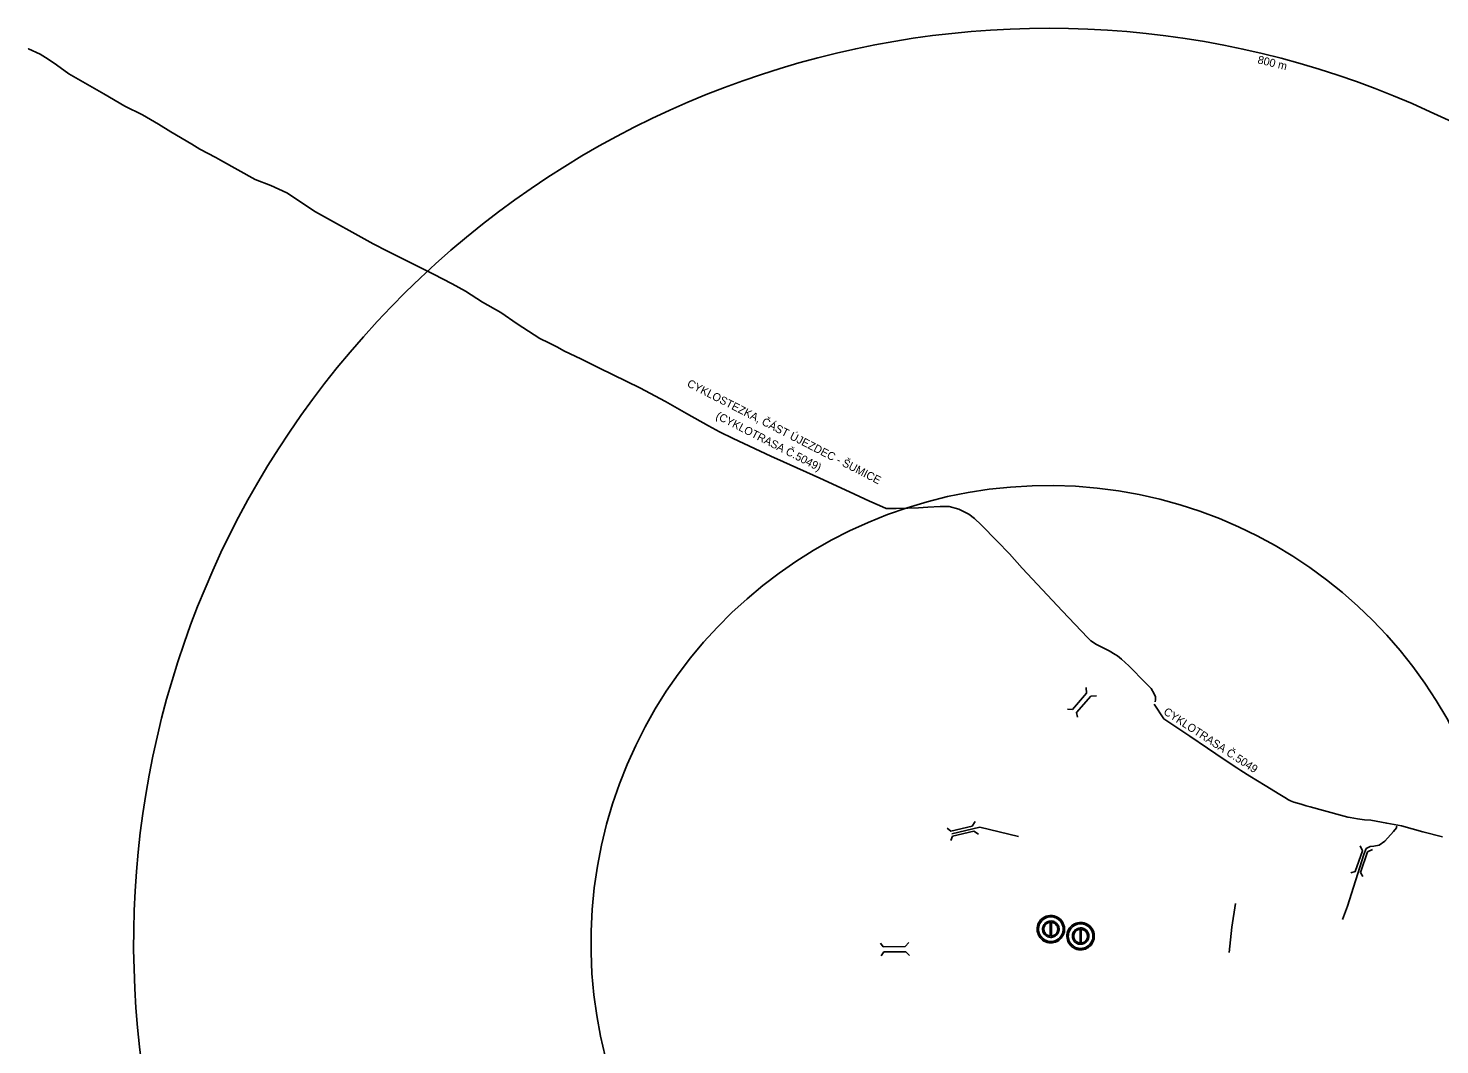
# Model space of a CAD drawing. Extents: x -520790 to -517278, y -1190021 to -1185077.
# Drawn here: x -520790 to -519555, y -1187341 to -1186452 of the extents above; entities that cross this region are included whole.
import ezdxf

# ---------------------------------------------------------------- set-up
doc = ezdxf.new("R2010")
doc.units = 0
for name, color, linetype in [('cyklostezka_s', 7, 'Continuous'), ('dostupnost_s', 7, 'Continuous'), ('most_s', 7, 'Continuous'), ('stezka_s', 7, 'Continuous'), ('zast_HD_s', 7, 'Continuous')]:
    doc.layers.add(name, color=color, linetype=linetype)

msp = doc.modelspace()

# ---------------------------------------------------------------- linework, layer by layer
at = {"layer": 'cyklostezka_s'}
for points in [[(-520790, -1186469.9), (-520789.7, -1186470), (-520779.6, -1186474.9), (-520772.5, -1186479.2), (-520765.3, -1186484.1), (-520754.5, -1186492), (-520740.3, -1186500.1), (-520724, -1186509.5), (-520705.4, -1186520.3), (-520690, -1186527.9), (-520676.1, -1186536), (-520665.4, -1186542.6), (-520647, -1186553.5), (-520639.8, -1186557.9), (-520625.8, -1186565.3), (-520621.8, -1186567.6), (-520606.7, -1186576.1), (-520591.6, -1186584.3), (-520577.7, -1186589.6), (-520563.9, -1186596.2), (-520538.7, -1186612.6), (-520488.3, -1186640.8), (-520475.8, -1186647.1), (-520435.6, -1186667.3), (-520419.3, -1186675.7), (-520407.6, -1186682.2), (-520392.6, -1186691.6), (-520376.7, -1186700.9), (-520362.3, -1186710.6), (-520342.5, -1186723.4), (-520334.6, -1186727.4), (-520327.6, -1186730.9), (-520321, -1186734.5), (-520306.8, -1186741.3), (-520290.5, -1186749.4), (-520255.1, -1186766.6), (-520232.5, -1186778.7), (-520214.3, -1186789.2), (-520195.1, -1186800), (-520185.3, -1186805.3), (-520173.5, -1186811), (-520140.6, -1186826.4), (-520129.4, -1186831.4), (-520097.7, -1186845.7), (-520071.8, -1186857.6), (-520054.2, -1186865.7), (-520045.6, -1186869.7), (-520039.5, -1186872.2), (-520030.9, -1186872.2), (-520020.8, -1186871.9), (-520011.4, -1186871.7), (-520003.3, -1186871.2), (-519992.5, -1186870.4), (-519984.4, -1186870.5), (-519976.2, -1186872.8), (-519967.3, -1186877.1), (-519962.3, -1186880.9), (-519956.6, -1186886.6), (-519942.5, -1186900.9), (-519931.8, -1186911.8), (-519920.8, -1186924.5), (-519885.4, -1186962), (-519863.4, -1186985.1), (-519860.5, -1186987.9), (-519855.6, -1186991.3), (-519844.7, -1186996.8), (-519839.2, -1186999.9), (-519837.2, -1187001.2), (-519833.9, -1187004.1), (-519827.4, -1187009.8), (-519812.6, -1187024.9), (-519808, -1187029.7), (-519805.1, -1187034.4), (-519804.2, -1187037), (-519804, -1187039.5), (-519804.3, -1187041.5)], [(-519805.2, -1187043.5), (-519796.9, -1187056.3), (-519789, -1187061.6), (-519774, -1187071.5), (-519758.5, -1187081.8), (-519758.5, -1187081.8), (-519744, -1187091.7), (-519733, -1187099.2), (-519729.5, -1187101.4), (-519721.6, -1187106.3), (-519708.2, -1187114.6), (-519695.4, -1187122.5), (-519691, -1187125.2), (-519687.8, -1187127.1), (-519686.1, -1187127.9), (-519683.1, -1187129.1), (-519676.8, -1187130.9), (-519672.4, -1187132.3), (-519668.7, -1187133.3), (-519642.4, -1187140.5), (-519635.9, -1187142.4), (-519633.9, -1187142.7), (-519627.3, -1187143.8), (-519621.3, -1187144.5), (-519615.8, -1187144.8), (-519601.8, -1187147.6), (-519588.9, -1187149.7), (-519570.3, -1187155.1), (-519553.1, -1187159.4)]]:
    msp.add_lwpolyline(points, dxfattribs=at)
at = {"layer": 'dostupnost_s'}
for radius, start, end in [(800, 53.8723, 292.3308), (400, 5.5181, 340.685)]:
    msp.add_arc((-519897.8, -1187252.1), radius, start, end, dxfattribs=at)
at = {"layer": 'most_s'}
for points in [[(-519864.7, -1187028.9), (-519864.3, -1187033.8), (-519876.8, -1187048.2), (-519880.9, -1187047.9)], [(-519855.7, -1187036.1), (-519860.5, -1187036.4), (-519873.1, -1187050.8), (-519872.2, -1187054.8)], [(-519961.9, -1187146.1), (-519964.5, -1187150.2), (-519983.1, -1187154.6), (-519986.2, -1187151.9)], [(-519958.9, -1187157.2), (-519963, -1187154.6), (-519981.6, -1187158.9), (-519983.2, -1187162.7)], [(-519625.2, -1187167.3), (-519623.1, -1187171.6), (-519629.3, -1187189.7), (-519633.2, -1187190.9)], [(-519614.2, -1187170.6), (-519618.6, -1187172.7), (-519624.9, -1187190.7), (-519622.6, -1187194.1)], [(-520019.7, -1187251.9), (-520023.1, -1187255.4), (-520042.2, -1187255.7), (-520044.6, -1187252.4)], [(-520019.1, -1187263.3), (-520022.5, -1187260), (-520041.6, -1187260.2), (-520044, -1187263.5)]]:
    msp.add_lwpolyline(points, dxfattribs=at)
at = {"layer": 'stezka_s'}
for points in [[(-519982.1, -1187156.7), (-519957.8, -1187151.1), (-519923.9, -1187159.3)], [(-519593.1, -1187150.1), (-519593.2, -1187150.9), (-519593.3, -1187151.6), (-519596, -1187154.7), (-519603.5, -1187163.3), (-519608.5, -1187166.7), (-519613, -1187167.6), (-519616.4, -1187167.8), (-519619.9, -1187169.8), (-519622, -1187175), (-519636.2, -1187220.1), (-519640.4, -1187231.7)], [(-519734, -1187217.8), (-519737.2, -1187238.5), (-519739.7, -1187260.8)]]:
    msp.add_lwpolyline(points, dxfattribs=at)
at = {"layer": 'zast_HD_s'}
for p, q in [((-519895, -1187247.4), (-519895, -1187247.4)), ((-519869, -1187253.5), (-519869, -1187253.5))]:
    msp.add_line(p, q, dxfattribs=at)
for points in [[(-519895.6, -1187228.2), (-519896.6, -1187228.3), (-519898.1, -1187228.5), (-519899.6, -1187228.9), (-519901, -1187229.5), (-519902.3, -1187230.2), (-519903.5, -1187231.2), (-519904.6, -1187232.2), (-519905.5, -1187233.4), (-519906.3, -1187234.7), (-519906.9, -1187236.1), (-519907.3, -1187237.6), (-519907.6, -1187239.1), (-519907.6, -1187240.6), (-519907.5, -1187242.1), (-519907.1, -1187243.6), (-519906.6, -1187245), (-519905.9, -1187246.4), (-519905.1, -1187247.6), (-519904.1, -1187248.8), (-519902.9, -1187249.8), (-519901.7, -1187250.6), (-519900.3, -1187251.3), (-519898.9, -1187251.8), (-519897.4, -1187252.1), (-519895.9, -1187252.2), (-519894.3, -1187252.2), (-519892.9, -1187251.9), (-519891.4, -1187251.5), (-519890, -1187250.9), (-519888.7, -1187250.1), (-519887.5, -1187249.1), (-519886.5, -1187248), (-519885.6, -1187246.8), (-519884.8, -1187245.5), (-519884.2, -1187244.1), (-519883.8, -1187242.6), (-519883.6, -1187241.1), (-519883.6, -1187239.6), (-519883.8, -1187238.1), (-519884.2, -1187236.6), (-519884.7, -1187235.2), (-519885.4, -1187233.9), (-519886.3, -1187232.6), (-519887.3, -1187231.5), (-519888.5, -1187230.5), (-519889.8, -1187229.7), (-519891.2, -1187229.1), (-519892.6, -1187228.6), (-519894.1, -1187228.3), (-519895.6, -1187228.2)], [(-519884.8, -1187240.2), (-519884.9, -1187238.9), (-519885.1, -1187237.5), (-519885.6, -1187236.2), (-519886.2, -1187235), (-519886.9, -1187233.8), (-519887.8, -1187232.8), (-519888.8, -1187231.9), (-519889.9, -1187231.1), (-519891.1, -1187230.4), (-519892.4, -1187229.9), (-519893.7, -1187229.6), (-519895, -1187229.4), (-519896.4, -1187229.4), (-519897.8, -1187229.6), (-519899.1, -1187230), (-519900.3, -1187230.5), (-519901.5, -1187231.2), (-519902.6, -1187232), (-519903.6, -1187233), (-519904.5, -1187234), (-519905.2, -1187235.2), (-519905.7, -1187236.4), (-519906.1, -1187237.7), (-519906.4, -1187239.1), (-519906.4, -1187240.5), (-519906.3, -1187241.8), (-519906, -1187243.2), (-519905.6, -1187244.4), (-519904.9, -1187245.7), (-519904.2, -1187246.8), (-519903.3, -1187247.8), (-519902.3, -1187248.7), (-519901.1, -1187249.5), (-519899.9, -1187250.1), (-519898.6, -1187250.6), (-519897.3, -1187250.9), (-519895.9, -1187251), (-519894.6, -1187251), (-519893.2, -1187250.8), (-519891.9, -1187250.4), (-519890.7, -1187249.8), (-519889.5, -1187249.1), (-519888.4, -1187248.3), (-519887.5, -1187247.3), (-519886.6, -1187246.2), (-519885.9, -1187245.1), (-519885.4, -1187243.8), (-519885, -1187242.5), (-519884.8, -1187241.1), (-519884.8, -1187240.2)], [(-519895.6, -1187229.4), (-519894.7, -1187229.5), (-519893.4, -1187229.7), (-519892, -1187230), (-519890.8, -1187230.6), (-519889.6, -1187231.2), (-519888.5, -1187232.1), (-519887.5, -1187233), (-519886.7, -1187234.1), (-519886, -1187235.3), (-519885.4, -1187236.5), (-519885.1, -1187237.8), (-519884.8, -1187239.2), (-519884.8, -1187240.6), (-519884.9, -1187241.9), (-519885.2, -1187243.3), (-519885.7, -1187244.5), (-519886.3, -1187245.8), (-519887.1, -1187246.9), (-519888, -1187247.9), (-519889, -1187248.8), (-519890.2, -1187249.6), (-519891.4, -1187250.2), (-519892.7, -1187250.6), (-519894, -1187250.9), (-519895.4, -1187251), (-519896.7, -1187251), (-519898.1, -1187250.7), (-519899.4, -1187250.3), (-519900.6, -1187249.8), (-519901.8, -1187249.1), (-519902.9, -1187248.2), (-519903.8, -1187247.2), (-519904.6, -1187246.2), (-519905.3, -1187245), (-519905.8, -1187243.7), (-519906.2, -1187242.4), (-519906.4, -1187241), (-519906.4, -1187239.7), (-519906.2, -1187238.3), (-519905.9, -1187237), (-519905.4, -1187235.7), (-519904.8, -1187234.5), (-519904, -1187233.4), (-519903, -1187232.4), (-519902, -1187231.5), (-519900.8, -1187230.8), (-519899.6, -1187230.2), (-519898.3, -1187229.8), (-519897, -1187229.5), (-519895.6, -1187229.4)], [(-519896.2, -1187233.1), (-519897.1, -1187233.2), (-519898, -1187233.4), (-519898.8, -1187233.8), (-519899.6, -1187234.3), (-519900.3, -1187234.8), (-519901, -1187235.5), (-519901.5, -1187236.2), (-519902, -1187237), (-519902.4, -1187237.8), (-519902.6, -1187238.7), (-519902.8, -1187239.6), (-519902.8, -1187240.5), (-519902.7, -1187241.4), (-519902.5, -1187242.3), (-519902.2, -1187243.1), (-519901.8, -1187243.9), (-519901.3, -1187244.7), (-519900.6, -1187245.3), (-519900, -1187245.9), (-519899.2, -1187246.4), (-519898.4, -1187246.9), (-519897.5, -1187247.1), (-519896.6, -1187247.3), (-519895.7, -1187247.4), (-519895, -1187247.4)], [(-519896.2, -1187246.2), (-519896.9, -1187246.1), (-519897.7, -1187245.9), (-519898.4, -1187245.6), (-519899, -1187245.2), (-519899.6, -1187244.7), (-519900.2, -1187244.2), (-519900.6, -1187243.6), (-519901, -1187242.9), (-519901.3, -1187242.2), (-519901.5, -1187241.5), (-519901.6, -1187240.7), (-519901.6, -1187240), (-519901.6, -1187239.2), (-519901.4, -1187238.5), (-519901.1, -1187237.8), (-519900.8, -1187237.1), (-519900.3, -1187236.5), (-519899.8, -1187235.9), (-519899.2, -1187235.4), (-519898.6, -1187235), (-519897.9, -1187234.6), (-519897.2, -1187234.4), (-519896.4, -1187234.2), (-519896.2, -1187234.2)], [(-519895, -1187247.4), (-519894.1, -1187247.2), (-519893.2, -1187247), (-519892.4, -1187246.6), (-519891.6, -1187246.2), (-519890.9, -1187245.6), (-519890.2, -1187245), (-519889.7, -1187244.3), (-519889.2, -1187243.5), (-519888.8, -1187242.7), (-519888.6, -1187241.8), (-519888.4, -1187240.9), (-519888.4, -1187240), (-519888.5, -1187239.1), (-519888.7, -1187238.2), (-519889, -1187237.3), (-519889.4, -1187236.5), (-519890, -1187235.8), (-519890.6, -1187235.1), (-519891.2, -1187234.5), (-519892, -1187234), (-519892.8, -1187233.6), (-519893.7, -1187233.3), (-519894.6, -1187233.1), (-519895.5, -1187233), (-519896.2, -1187233.1)], [(-519896.2, -1187233.1), (-519896.2, -1187246.2)], [(-519896.2, -1187234.2), (-519896.2, -1187233.1)], [(-519895.6, -1187228.2), (-519895.6, -1187229.4)], [(-519895.6, -1187229.4), (-519895.6, -1187228.2)], [(-519895, -1187247.4), (-519895, -1187234.2)], [(-519895, -1187234.2), (-519894.3, -1187234.3), (-519893.5, -1187234.6), (-519892.8, -1187234.9), (-519892.2, -1187235.2), (-519891.6, -1187235.7), (-519891.1, -1187236.3), (-519890.6, -1187236.9), (-519890.2, -1187237.5), (-519889.9, -1187238.2), (-519889.7, -1187239), (-519889.6, -1187239.7), (-519889.6, -1187240.5), (-519889.7, -1187241.2), (-519889.8, -1187242), (-519890.1, -1187242.7), (-519890.5, -1187243.4), (-519890.9, -1187244), (-519891.4, -1187244.6), (-519892, -1187245.1), (-519892.6, -1187245.5), (-519893.3, -1187245.8), (-519894, -1187246.1), (-519894.8, -1187246.2), (-519895, -1187246.2)], [(-519869.6, -1187234.3), (-519870.6, -1187234.4), (-519872.1, -1187234.6), (-519873.5, -1187235), (-519874.9, -1187235.6), (-519876.3, -1187236.4), (-519877.5, -1187237.3), (-519878.5, -1187238.3), (-519879.5, -1187239.5), (-519880.3, -1187240.8), (-519880.9, -1187242.2), (-519881.3, -1187243.7), (-519881.5, -1187245.2), (-519881.6, -1187246.7), (-519881.4, -1187248.2), (-519881.1, -1187249.7), (-519880.6, -1187251.1), (-519879.9, -1187252.5), (-519879, -1187253.7), (-519878, -1187254.9), (-519876.9, -1187255.9), (-519875.6, -1187256.7), (-519874.3, -1187257.4), (-519872.8, -1187257.9), (-519871.3, -1187258.2), (-519869.8, -1187258.3), (-519868.3, -1187258.3), (-519866.8, -1187258), (-519865.4, -1187257.6), (-519864, -1187257), (-519862.7, -1187256.2), (-519861.5, -1187255.2), (-519860.4, -1187254.1), (-519859.5, -1187252.9), (-519858.8, -1187251.6), (-519858.2, -1187250.2), (-519857.8, -1187248.7), (-519857.6, -1187247.2), (-519857.6, -1187245.7), (-519857.8, -1187244.2), (-519858.1, -1187242.7), (-519858.7, -1187241.3), (-519859.4, -1187240), (-519860.3, -1187238.7), (-519861.3, -1187237.6), (-519862.5, -1187236.7), (-519863.7, -1187235.8), (-519865.1, -1187235.2), (-519866.6, -1187234.7), (-519868.1, -1187234.4), (-519869.6, -1187234.3)], [(-519858.8, -1187246.3), (-519858.9, -1187245), (-519859.1, -1187243.6), (-519859.5, -1187242.3), (-519860.1, -1187241.1), (-519860.9, -1187239.9), (-519861.7, -1187238.9), (-519862.7, -1187238), (-519863.8, -1187237.2), (-519865, -1187236.5), (-519866.3, -1187236), (-519867.6, -1187235.7), (-519869, -1187235.5), (-519870.4, -1187235.6), (-519871.7, -1187235.7), (-519873, -1187236.1), (-519874.3, -1187236.6), (-519875.5, -1187237.3), (-519876.6, -1187238.1), (-519877.6, -1187239.1), (-519878.4, -1187240.1), (-519879.1, -1187241.3), (-519879.7, -1187242.5), (-519880.1, -1187243.8), (-519880.3, -1187245.2), (-519880.4, -1187246.6), (-519880.3, -1187247.9), (-519880, -1187249.3), (-519879.5, -1187250.5), (-519878.9, -1187251.8), (-519878.2, -1187252.9), (-519877.3, -1187253.9), (-519876.2, -1187254.8), (-519875.1, -1187255.6), (-519873.9, -1187256.2), (-519872.6, -1187256.7), (-519871.3, -1187257), (-519869.9, -1187257.1), (-519868.5, -1187257.1), (-519867.2, -1187256.9), (-519865.9, -1187256.5), (-519864.6, -1187255.9), (-519863.5, -1187255.2), (-519862.4, -1187254.4), (-519861.4, -1187253.4), (-519860.6, -1187252.3), (-519859.9, -1187251.2), (-519859.4, -1187249.9), (-519859, -1187248.6), (-519858.8, -1187247.2), (-519858.8, -1187246.3)], [(-519869.6, -1187235.5), (-519868.7, -1187235.6), (-519867.3, -1187235.8), (-519866, -1187236.1), (-519864.7, -1187236.7), (-519863.6, -1187237.3), (-519862.5, -1187238.2), (-519861.5, -1187239.1), (-519860.7, -1187240.2), (-519860, -1187241.4), (-519859.4, -1187242.6), (-519859, -1187244), (-519858.8, -1187245.3), (-519858.8, -1187246.7), (-519858.9, -1187248), (-519859.2, -1187249.4), (-519859.7, -1187250.6), (-519860.3, -1187251.9), (-519861.1, -1187253), (-519862, -1187254), (-519863, -1187254.9), (-519864.1, -1187255.7), (-519865.4, -1187256.3), (-519866.6, -1187256.7), (-519868, -1187257), (-519869.3, -1187257.1), (-519870.7, -1187257.1), (-519872.1, -1187256.9), (-519873.4, -1187256.5), (-519874.6, -1187255.9), (-519875.8, -1187255.2), (-519876.8, -1187254.3), (-519877.8, -1187253.4), (-519878.6, -1187252.3), (-519879.3, -1187251.1), (-519879.8, -1187249.8), (-519880.2, -1187248.5), (-519880.4, -1187247.1), (-519880.4, -1187245.8), (-519880.2, -1187244.4), (-519879.9, -1187243.1), (-519879.4, -1187241.8), (-519878.7, -1187240.6), (-519877.9, -1187239.5), (-519877, -1187238.5), (-519876, -1187237.6), (-519874.8, -1187236.9), (-519873.6, -1187236.3), (-519872.3, -1187235.9), (-519870.9, -1187235.6), (-519869.6, -1187235.5)], [(-519869.6, -1187234.3), (-519869.6, -1187235.5)], [(-519869.6, -1187235.5), (-519869.6, -1187234.3)], [(-519895, -1187246.2), (-519895, -1187247.4)], [(-519870.2, -1187239.2), (-519871.1, -1187239.3), (-519872, -1187239.6), (-519872.8, -1187239.9), (-519873.6, -1187240.4), (-519874.3, -1187240.9), (-519875, -1187241.6), (-519875.5, -1187242.3), (-519876, -1187243.1), (-519876.3, -1187243.9), (-519876.6, -1187244.8), (-519876.7, -1187245.7), (-519876.8, -1187246.6), (-519876.7, -1187247.5), (-519876.5, -1187248.4), (-519876.2, -1187249.2), (-519875.7, -1187250), (-519875.2, -1187250.8), (-519874.6, -1187251.5), (-519873.9, -1187252), (-519873.2, -1187252.6), (-519872.4, -1187253), (-519871.5, -1187253.3), (-519870.6, -1187253.4), (-519869.7, -1187253.5), (-519869, -1187253.5)], [(-519870.1, -1187252.3), (-519870.9, -1187252.2), (-519871.6, -1187252), (-519872.3, -1187251.7), (-519873, -1187251.3), (-519873.6, -1187250.8), (-519874.1, -1187250.3), (-519874.6, -1187249.7), (-519875, -1187249), (-519875.3, -1187248.3), (-519875.5, -1187247.6), (-519875.6, -1187246.8), (-519875.6, -1187246.1), (-519875.5, -1187245.3), (-519875.3, -1187244.6), (-519875.1, -1187243.9), (-519874.7, -1187243.2), (-519874.3, -1187242.6), (-519873.8, -1187242), (-519873.2, -1187241.5), (-519872.6, -1187241.1), (-519871.9, -1187240.7), (-519871.1, -1187240.5), (-519870.4, -1187240.4), (-519870.2, -1187240.3)], [(-519870.2, -1187240.3), (-519870.2, -1187239.2)], [(-519869, -1187253.5), (-519868.1, -1187253.4), (-519867.2, -1187253.1), (-519866.3, -1187252.8), (-519865.6, -1187252.3), (-519864.8, -1187251.7), (-519864.2, -1187251.1), (-519863.6, -1187250.4), (-519863.2, -1187249.6), (-519862.8, -1187248.8), (-519862.6, -1187247.9), (-519862.4, -1187247), (-519862.4, -1187246.1), (-519862.5, -1187245.2), (-519862.7, -1187244.3), (-519863, -1187243.4), (-519863.4, -1187242.6), (-519863.9, -1187241.9), (-519864.5, -1187241.2), (-519865.2, -1187240.6), (-519866, -1187240.1), (-519866.8, -1187239.7), (-519867.6, -1187239.4), (-519868.5, -1187239.2), (-519869.4, -1187239.1), (-519870.1, -1187239.2)], [(-519870.1, -1187239.2), (-519870.1, -1187252.3)], [(-519869, -1187253.5), (-519869, -1187240.3)], [(-519869, -1187240.3), (-519868.2, -1187240.4), (-519867.5, -1187240.7), (-519866.8, -1187241), (-519866.2, -1187241.4), (-519865.6, -1187241.8), (-519865, -1187242.4), (-519864.6, -1187243), (-519864.2, -1187243.6), (-519863.9, -1187244.3), (-519863.7, -1187245.1), (-519863.6, -1187245.8), (-519863.5, -1187246.6), (-519863.6, -1187247.4), (-519863.8, -1187248.1), (-519864.1, -1187248.8), (-519864.4, -1187249.5), (-519864.9, -1187250.1), (-519865.4, -1187250.7), (-519866, -1187251.2), (-519866.6, -1187251.6), (-519867.3, -1187251.9), (-519868, -1187252.2), (-519868.8, -1187252.3), (-519869, -1187252.3)], [(-519869, -1187252.3), (-519869, -1187253.5)]]:
    msp.add_lwpolyline(points, dxfattribs=at)

# ---------------------------------------------------------------- texts
at = {"layer": 'cyklostezka_s'}
for s, rotation, p in [('CYKLOSTEZKA, ČÁST ÚJEZDEC - ŠUMICE', 332.8503, (-520214.4, -1186765.1)), ('(CYKLOTRASA Č.5049)', 332.8503, (-520189.3, -1186793.3)), ('CYKLOTRASA Č.5049', 326.8564, (-519797.7, -1187051.7))]:
    msp.add_text(s, height=7, rotation=rotation, dxfattribs=at).set_placement(p)
at = {"layer": 'dostupnost_s'}
msp.add_text('800 m', height=7, rotation=346.4234, dxfattribs=at).set_placement((-519715.2, -1186482.7))

doc.saveas('drawing.dxf')
